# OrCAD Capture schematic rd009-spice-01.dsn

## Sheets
1 PAGE3: size A
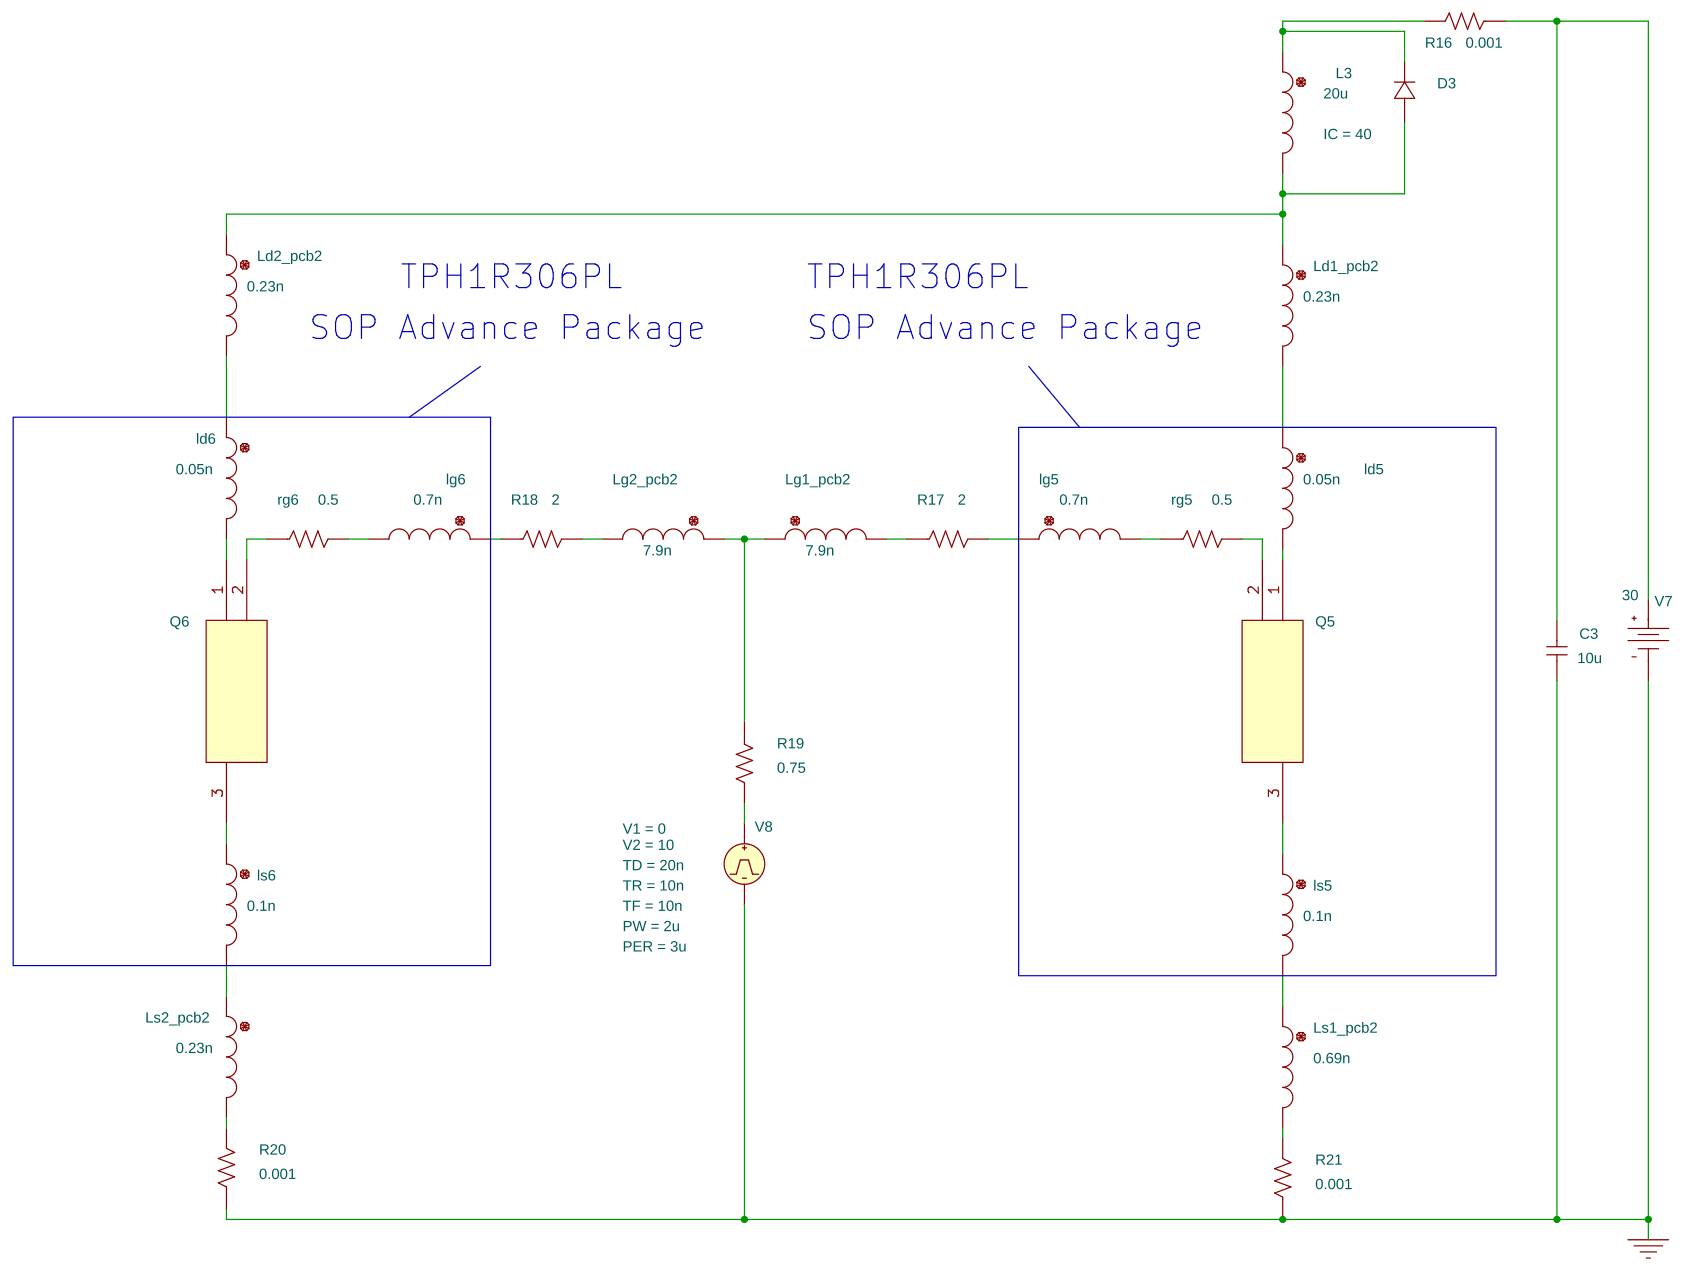
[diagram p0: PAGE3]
2 PAGE2: size A
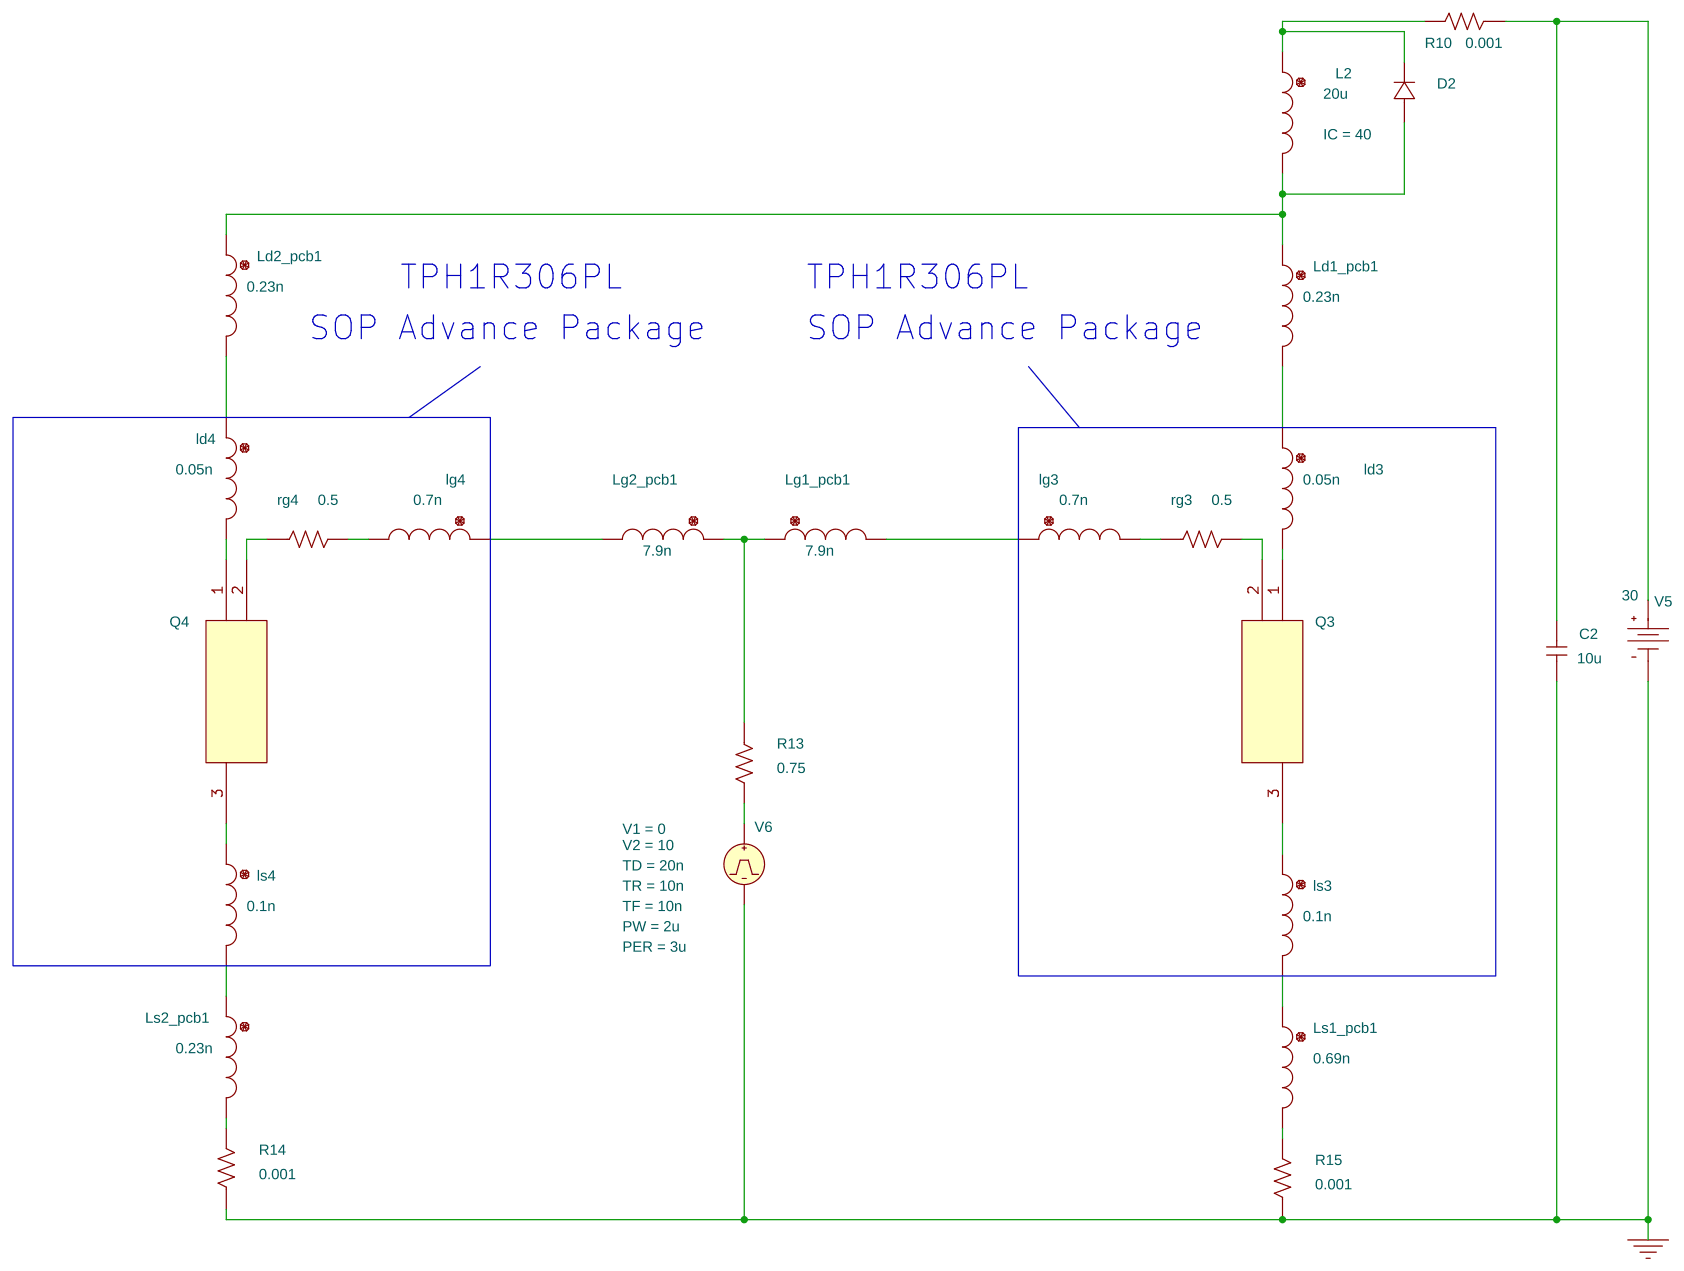
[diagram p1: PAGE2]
3 PAGE1: size B
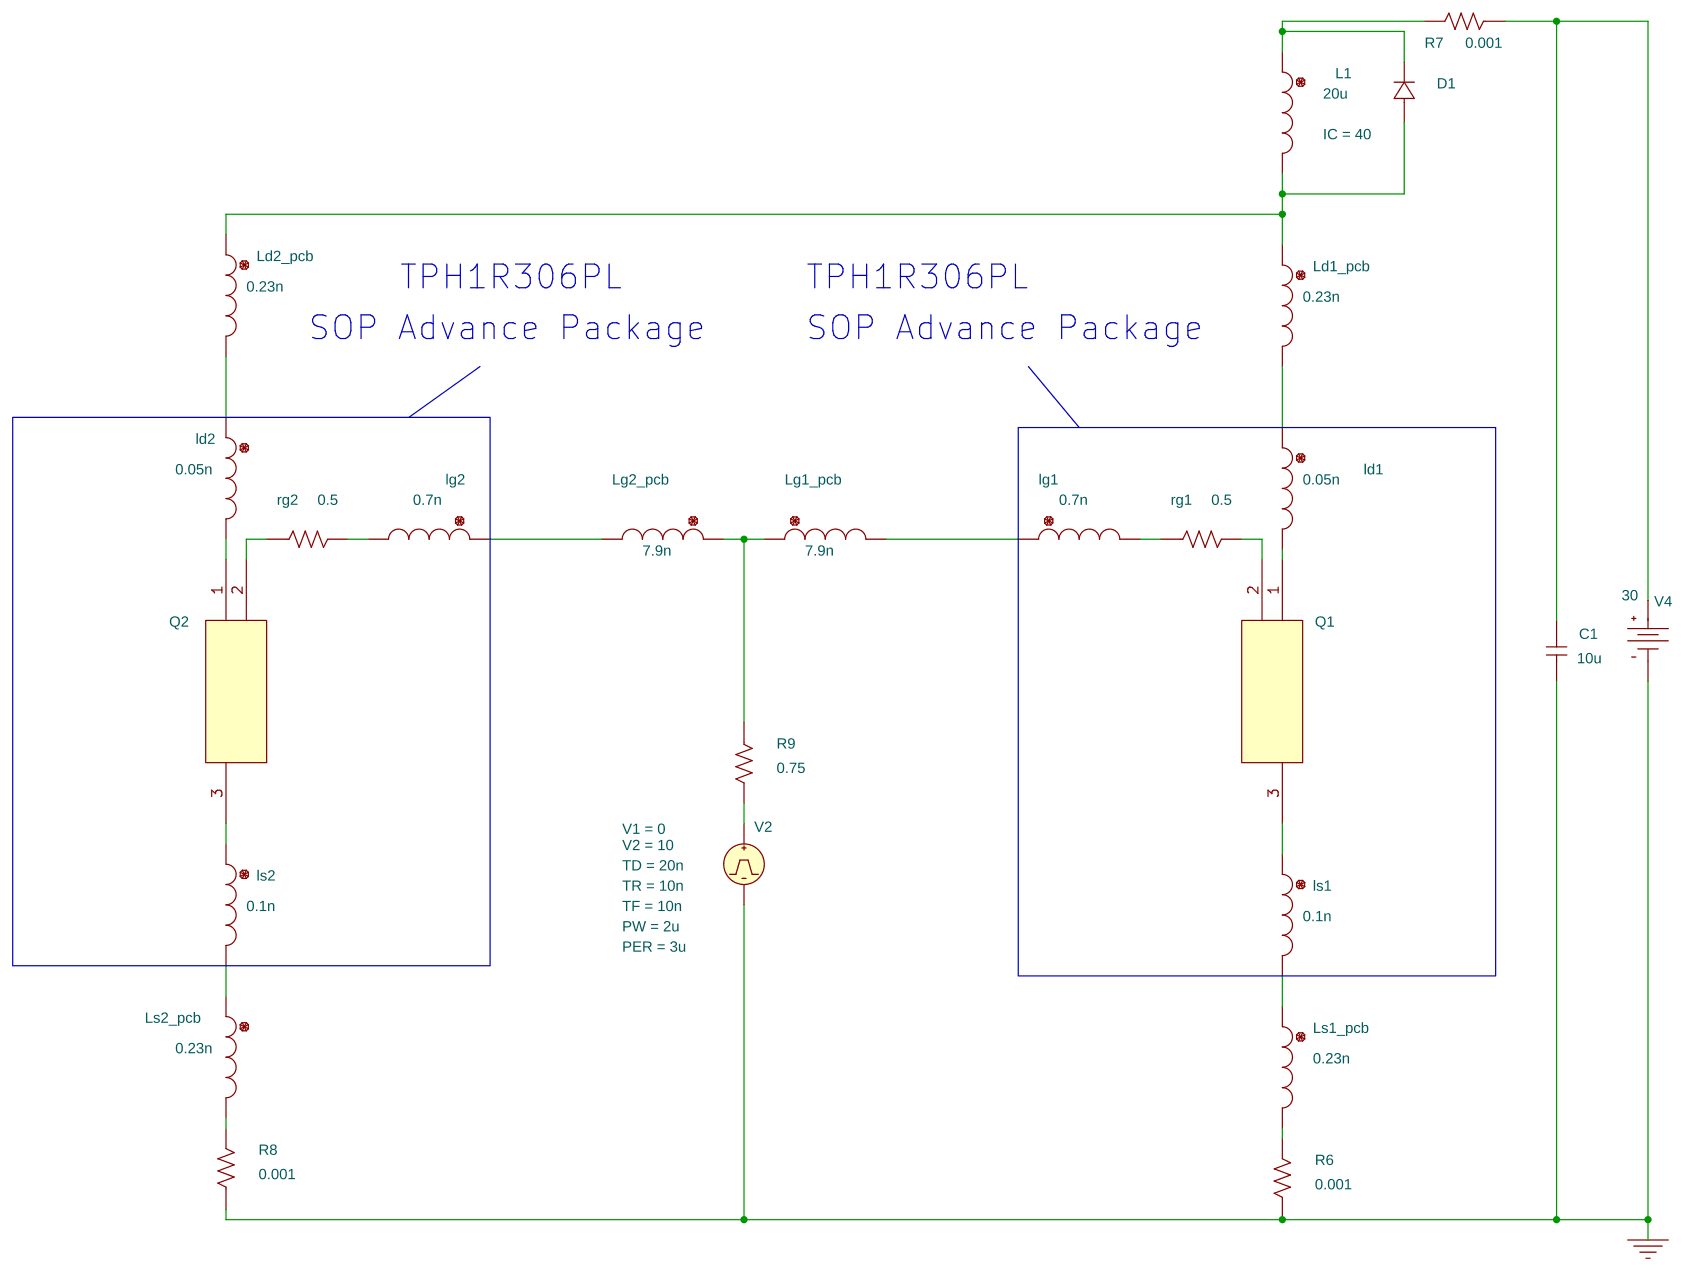
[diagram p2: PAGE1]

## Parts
sheet PAGE1
C1  10u  [RAD/CK05]
D1  Dbreak
L1  20u  [DISC/.350x.175/LS.200x.100/.034]
ld1  0.05n  [DISC/.350x.175/LS.200x.100/.034]
Ld1_pcb  0.23n  [DISC/.350x.175/LS.200x.100/.034]
ld2  0.05n  [DISC/.350x.175/LS.200x.100/.034]
Ld2_pcb  0.23n  [DISC/.350x.175/LS.200x.100/.034]
lg1  0.7n  [DISC/.350x.175/LS.200x.100/.034]
Lg1_pcb  7.9n  [DISC/.350x.175/LS.200x.100/.034]
lg2  0.7n  [DISC/.350x.175/LS.200x.100/.034]
Lg2_pcb  7.9n  [DISC/.350x.175/LS.200x.100/.034]
ls1  0.1n  [DISC/.350x.175/LS.200x.100/.034]
Ls1_pcb  0.23n  [DISC/.350x.175/LS.200x.100/.034]
ls2  0.1n  [DISC/.350x.175/LS.200x.100/.034]
Ls2_pcb  0.23n  [DISC/.350x.175/LS.200x.100/.034]
Q1  NMOS_TPH1R306PL
Q2  NMOS_TPH1R306PL
R6  0.001  [AX/RC05]
R7  0.001  [AX/RC05]
R8  0.001  [AX/RC05]
R9  0.75  [AX/RC05]
rg1  0.5  [AX/RC05]
rg2  0.5  [AX/RC05]
V2  VPULSE
V4  VDC
sheet PAGE2
C2  10u  [RAD/CK05]
D2  Dbreak
L2  20u  [DISC/.350x.175/LS.200x.100/.034]
Ld1_pcb1  0.23n  [DISC/.350x.175/LS.200x.100/.034]
Ld2_pcb1  0.23n  [DISC/.350x.175/LS.200x.100/.034]
ld3  0.05n  [DISC/.350x.175/LS.200x.100/.034]
ld4  0.05n  [DISC/.350x.175/LS.200x.100/.034]
Lg1_pcb1  7.9n  [DISC/.350x.175/LS.200x.100/.034]
Lg2_pcb1  7.9n  [DISC/.350x.175/LS.200x.100/.034]
lg3  0.7n  [DISC/.350x.175/LS.200x.100/.034]
lg4  0.7n  [DISC/.350x.175/LS.200x.100/.034]
Ls1_pcb1  0.69n  [DISC/.350x.175/LS.200x.100/.034]
Ls2_pcb1  0.23n  [DISC/.350x.175/LS.200x.100/.034]
ls3  0.1n  [DISC/.350x.175/LS.200x.100/.034]
ls4  0.1n  [DISC/.350x.175/LS.200x.100/.034]
Q3  NMOS_TPH1R306PL
Q4  NMOS_TPH1R306PL
R10  0.001  [AX/RC05]
R13  0.75  [AX/RC05]
R14  0.001  [AX/RC05]
R15  0.001  [AX/RC05]
rg3  0.5  [AX/RC05]
rg4  0.5  [AX/RC05]
V5  VDC
V6  VPULSE
sheet PAGE3
C3  10u  [RAD/CK05]
D3  Dbreak
L3  20u  [DISC/.350x.175/LS.200x.100/.034]
Ld1_pcb2  0.23n  [DISC/.350x.175/LS.200x.100/.034]
Ld2_pcb2  0.23n  [DISC/.350x.175/LS.200x.100/.034]
ld5  0.05n  [DISC/.350x.175/LS.200x.100/.034]
ld6  0.05n  [DISC/.350x.175/LS.200x.100/.034]
Lg1_pcb2  7.9n  [DISC/.350x.175/LS.200x.100/.034]
Lg2_pcb2  7.9n  [DISC/.350x.175/LS.200x.100/.034]
lg5  0.7n  [DISC/.350x.175/LS.200x.100/.034]
lg6  0.7n  [DISC/.350x.175/LS.200x.100/.034]
Ls1_pcb2  0.69n  [DISC/.350x.175/LS.200x.100/.034]
Ls2_pcb2  0.23n  [DISC/.350x.175/LS.200x.100/.034]
ls5  0.1n  [DISC/.350x.175/LS.200x.100/.034]
ls6  0.1n  [DISC/.350x.175/LS.200x.100/.034]
Q5  NMOS_TPH1R306PL
Q6  NMOS_TPH1R306PL
R16  0.001  [AX/RC05]
R17  2  [AX/RC05]
R18  2  [AX/RC05]
R19  0.75  [AX/RC05]
R20  0.001  [AX/RC05]
R21  0.001  [AX/RC05]
rg5  0.5  [AX/RC05]
rg6  0.5  [AX/RC05]
V7  VDC
V8  VPULSE

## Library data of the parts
C1-C3 = C
D1-D3 = Dbreak
L1-L3 = L: IC: 40
ld1 Ld1_pcb Ld1_pcb1 Ld1_pcb2 ld2 Ld2_pcb Ld2_pcb1 Ld2_pcb2 ld3-ld6 lg1 Lg1_pcb Lg1_pcb1 Lg1_pcb2 lg2 Lg2_pcb Lg2_pcb1 Lg2_pcb2 lg3-lg6 ls1 Ls1_pcb Ls1_pcb1 Ls1_pcb2 ls2 Ls2_pcb Ls2_pcb1 Ls2_pcb2 ls3-ls6 = L
Q1-Q6 = NMOS_TPH1R306PL
R6-R10 R13-R21 rg1-rg6 = R
V2 V6 V8 = VPULSE: PER: 3u; PW: 2u; TD: 20n; TF: 10n; TR: 10n; V1: 0; V2: 10
V4 V5 V7 = VDC: DC: 30

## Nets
0: C1.1 C2.1 C3.1 R6.1 R8.1 R14.1 R15.1 R20.1 R21.1 V2.2(-) V4.1(-) V5.1(-) V6.2(-) V7.1(-) V8.2(-)
N60308: D1.1(2) L1.1 R7.2
N60330: C1.2 R7.1 V4.0(+)
N60382: D1.0(1) L1.2 Ld1_pcb.1 Ld2_pcb.1
N60468: ld2.1 Ld2_pcb.2
N60480: ld1.1 Ld1_pcb.2
N60680: Q2.2 rg2.1
N60690: lg2.2 rg2.2
N60696: lg2.1 Lg2_pcb.2
N60702: Lg1_pcb.1 Lg2_pcb.1 R9.1
N60716: lg1.1 Lg1_pcb.2
N60722: lg1.2 rg1.1
N60728: Q1.2 rg1.2
N60738: ld2.2 Q2.1
N60744: ld1.2 Q1.1
N60850: R9.2 V2.1(+)
N60856: ls2.1 Q2.3
N60908: ls1.1 Q1.3
N60964: ls2.2 Ls2_pcb.1
N60970: ls1.2 Ls1_pcb.1
N61020: Ls2_pcb.2 R8.2
N61026: Ls1_pcb.2 R6.2
N92157: D2.1(2) L2.1 R10.2
N92167: C2.2 R10.1 V5.0(+)
N92241: D2.0(1) L2.2 Ld1_pcb1.1 Ld2_pcb1.1
N92315: Ld2_pcb1.2 ld4.1
N92327: Ld1_pcb1.2 ld3.1
N92559: ld4.2 Q4.1
N92565: Q4.2 rg4.1
N92575: lg4.2 rg4.2
N92581: Lg2_pcb1.2 lg4.1
N92591: Lg1_pcb1.1 Lg2_pcb1.1 R13.1
N92605: Lg1_pcb1.2 lg3.1
N92615: lg3.2 rg3.1
N92621: Q3.2 rg3.2
N92631: ld3.2 Q3.1
N92769: R13.2 V6.1(+)
N92775: ls4.1 Q4.3
N92781: ls3.1 Q3.3
N92883: Ls2_pcb1.1 ls4.2
N92889: Ls1_pcb1.1 ls3.2
N92939: Ls2_pcb1.2 R14.2
N92945: Ls1_pcb1.2 R15.2
N94035: D3.1(2) L3.1 R16.2
N94057: C3.2 R16.1 V7.0(+)
N94119: D3.0(1) L3.2 Ld1_pcb2.1 Ld2_pcb2.1
N94193: Ld2_pcb2.2 ld6.1
N94205: Ld1_pcb2.2 ld5.1
N94437: ld6.2 Q6.1
N94443: Q6.2 rg6.1
N94453: lg6.2 rg6.2
N94459: lg6.1 R18.1
N94465: Lg2_pcb2.2 R18.2
N94469: Lg1_pcb2.1 Lg2_pcb2.1 R19.1
N94483: Lg1_pcb2.2 R17.1
N94489: lg5.1 R17.2
N94493: lg5.2 rg5.1
N94499: Q5.2 rg5.2
N94509: ld5.2 Q5.1
N94635: R19.2 V8.1(+)
N94641: ls6.1 Q6.3
N94647: ls5.1 Q5.3
N94761: Ls2_pcb2.1 ls6.2
N94767: Ls1_pcb2.1 ls5.2
N94817: Ls2_pcb2.2 R20.2
N94823: Ls1_pcb2.2 R21.2

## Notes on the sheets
sheet 1
- TPH1R306PL
- TPH1R306PL
- SOP Advance Package
- SOP Advance Package
sheet 2
- TPH1R306PL
- TPH1R306PL
- SOP Advance Package
- SOP Advance Package
sheet 3
- TPH1R306PL
- TPH1R306PL
- SOP Advance Package
- SOP Advance Package
